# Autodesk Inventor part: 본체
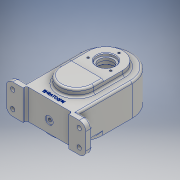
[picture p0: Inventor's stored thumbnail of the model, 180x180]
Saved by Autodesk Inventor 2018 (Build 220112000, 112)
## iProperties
Created: 2021-05
Part Number: 본체
Material: 알루미늄 6061
Document SubType Name: Modeling
Designer: Admin
Density: 2.7 g/cm^3
Appearance: 알루미늄 - 평지
Mass: 756.201 g
Surface Area: 581.914 cm^2
Volume: 280.074 cm^3
Author: Admin
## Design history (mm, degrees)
sketch "스케치1"
  geometry: L1 (0, 22.5)-(0, -22.5); L2 (-40, 22.5)-(-40, -22.5); L3 (40, -22.5)-(40, 22.5); L4 (-56, 0)-(56, 0) reference; L5 (0, -87.5)-(0, 87.5) reference; A1 r 40 centre (0, 22.5) between (40, 22.5) and (-40, 22.5); A2 r 40 centre (0, -22.5) between (-40, -22.5) and (40, -22.5); 2 further points
  constraints: 8 end point, 4 point on circle, 4 tangent, 2 centre point, 1 midpoint, 1 parallel, 1 vertical, 2 other
  dimensions: "d0" = 40 radius of A1; "d1" = 45 distance of L1.start L1.end
extrude "돌출1" new body sketch "스케치1" distance "d2" = 49; taper "d3" = 0 deg
sketch "스케치2"
  geometry: L1 (40, -22.5)-(40, -59.5); L2 (40, -59.5)-(61, -59.5); L3 (61, -59.5)-(61, -69.5); L4 (61, -69.5)-(35, -69.5); L5 (35, -69.5)-(35, -64.5); L6 (35, -64.5)-(-35, -64.5); L7 (-35, -64.5)-(-35, -69.5); L8 (-35, -69.5)-(-61, -69.5); L9 (-61, -69.5)-(-61, -59.5); L10 (-61, -59.5)-(-40, -59.5); L11 (-40, -22.5)-(-40, 22.5) reference; L12 (-40, -59.5)-(-40, -22.5); L13 (0, -96.5)-(0, 92.5) reference; A1 r 40 centre (0, -22.5) between (-40, -22.5) and (40, -22.5) reference; 1 further point
  constraints: 22 end point, 9 perpendicular, 1 collinear, 1 tangent, 1 vertical, 2 other
  dimensions: "d4" = 70 distance between parallel lines of L5 L7; "d5" = 10 distance of L8.end L9.end; "d6" = 10 distance of L2.end L3.end; "d7" = 47 distance from line of A1.centre L8; "d8" = 47 distance from line of A1.centre L4; "d9" = 5 distance between parallel lines of L6 L8; "d87" = 122 distance between parallel lines of L9 L3
extrude "돌출2" join sketch "스케치2" distance "d10" = 46; taper "d11" = 0 deg
node "작업 평면1"
sketch "스케치4"
  geometry: L1 (-40, -49)-(40, -49) reference; C1 r 6 at (0, -28); 1 further point
  constraints: 1 centre point
  dimensions: "d14" = 12 diameter of C1; "d15" = 21 distance from line of L1 C1.centre
extrude "돌출3" join sketch "스케치4" distance "d16" = 3; taper "d17" = 0 deg
sketch "스케치5"
  geometry: C1 r 6 at (0, -28); A1 r 6 centre (0, -28) between (0, -22) and (0, -34) reference; 1 further point
  constraints: 1 centre point, 1 coincident
  dimensions: "d18" = 12 diameter of C1
extrude "돌출4" join sketch "스케치5" distance "d19" = 3; taper "d20" = 0 deg
sketch "스케치6"
  geometry: L1 (0, 22.5)-(0, -22.5); L2 (-30, 22.5)-(-30, -22.5); L3 (30, -22.5)-(30, 22.5); A1 r 40 centre (0, 22.5) between (40, 22.5) and (-40, 22.5) reference; A2 r 40 centre (0, -22.5) between (-40, -22.5) and (40, -22.5) reference; A3 r 30 centre (0, 22.5) between (30, 22.5) and (-30, 22.5); A4 r 30 centre (0, -22.5) between (-30, -22.5) and (30, -22.5); 2 further points
  constraints: 8 end point, 4 point on circle, 4 tangent, 2 centre point, 1 midpoint, 1 parallel, 1 vertical
  dimensions: "d21" = 60 diameter of A4
extrude "돌출5" cut sketch "스케치6" distance "d22" = 41; taper "d23" = 0 deg
sketch "스케치7"
  geometry: L1 (0, 22.5)-(0, -22.5); L2 (-35, 22.5)-(-35, -22.5); L3 (35, -22.5)-(35, 22.5); A1 r 40 centre (0, 22.5) between (40, 22.5) and (-40, 22.5) reference; A2 r 40 centre (0, -22.5) between (-40, -22.5) and (40, -22.5) reference; A3 r 35 centre (0, 22.5) between (35, 22.5) and (-35, 22.5); A4 r 35 centre (0, -22.5) between (-35, -22.5) and (35, -22.5); 8 further points
  constraints: 8 end point, 6 point on circle, 4 coincident, 4 tangent, 2 centre point, 1 midpoint, 1 parallel, 1 vertical
  dimensions: "d24" = 70 diameter of A4
hole "구멍1" sketch "스케치7" at (0, 57.5), (35, 22.5), (-35, 22.5), (-35, -22.5), (0, -57.5), (35, -22.5) diameter "d25" = 3.242; stored, may be unused: countersink angle "d29" = 90 deg, drill point angle "d31" = 118 deg; dims "d26" = 8, "d27" = 4, "d28" = 2, "d30" = 10
sketch "스케치12"
  geometry: 1 further point
sketch "스케치13"
  geometry: L1 (0, 22.5)-(0, -22.5); L2 (-26, 22.5)-(-26, -22.5); L3 (26, -22.5)-(26, 22.5); A1 r 30 centre (0, 22.5) between (30, 22.5) and (-30, 22.5) reference; A2 r 30 centre (0, -22.5) between (-30, -22.5) and (30, -22.5) reference; A3 r 26 centre (0, 22.5) between (26, 22.5) and (-26, 22.5); A4 r 26 centre (0, -22.5) between (-26, -22.5) and (26, -22.5); 2 further points
  constraints: 8 end point, 4 point on circle, 4 tangent, 2 centre point, 1 midpoint, 1 parallel, 1 vertical
  dimensions: "d45" = 52 diameter of A4
extrude "돌출9" join sketch "스케치13" distance "d46" = 11; taper "d47" = 0 deg
sketch "스케치14"
  geometry: L1 (-26, 22.5)-(-26, -22.5) reference; L2 (26, 22.5)-(26, -22.5) reference; L3 (26, 22.5)-(26, -7.5); L4 (26, -7.5)-(-26, -7.5); L5 (-26, -7.5)-(-26, 22.5); A1 r 26 centre (0, 22.5) between (26, 22.5) and (-26, 22.5) reference; A2 r 26 centre (0, 22.5) between (26, 22.5) and (-26, 22.5); 1 further point
  constraints: 6 end point, 2 point on circle, 1 centre point, 1 coincident, 1 parallel, 1 point on line
  dimensions: "d48" = 30 distance from line of A2.centre L4
extrude "돌출10" cut sketch "스케치14" distance "d49" = 3; taper "d50" = 0 deg
sketch "스케치15"
  geometry: C1 r 14 at (0, 22.5); A1 r 26 centre (0, 22.5) between (26, 22.5) and (-26, 22.5) reference; 1 further point
  constraints: 1 centre point, 1 coincident
  dimensions: "d51" = 28 diameter of C1
extrude "돌출11" cut sketch "스케치15" distance "d52" = 4; taper "d53" = 0 deg
sketch "스케치16"
  geometry: C1 r 14 at (0, 0) reference; C2 r 11 at (0, 0); 1 further point
  constraints: 1 centre point, 1 coincident
  dimensions: "d54" = 22 diameter of C2
extrude "돌출12" cut sketch "스케치16" distance "d55" = 12; taper "d56" = 0 deg
sketch "스케치17"
  geometry: C1 r 11 at (0, 22.5) reference; C2 r 14 at (0, 22.5); 1 further point
  constraints: 1 centre point, 1 coincident
  dimensions: "d57" = 28 diameter of C2
extrude "돌출13" cut sketch "스케치17" distance "d58" = 8; taper "d59" = 0 deg
sketch "스케치18"
  geometry: C1 r 14 at (0, -22.5); A1 r 26 centre (0, -22.5) between (-26, -22.5) and (26, -22.5) reference; 1 further point
  constraints: 1 centre point, 1 coincident
  dimensions: "d60" = 28 diameter of C1
extrude "돌출14" cut sketch "스케치18" distance "d61" = 8; taper "d62" = 0 deg
sketch "스케치19"
  geometry: C1 r 14 at (0, 0) reference; C2 r 10 at (0, 0); 1 further point
  constraints: 1 centre point, 1 coincident
  dimensions: "d63" = 20 diameter of C2
extrude "돌출15" cut sketch "스케치19" distance "d64" = 4; taper "d65" = 0 deg
sketch "스케치20"
  geometry: C1 r 6 at (0, 0) reference; 2 further points
  constraints: 1 coincident
hole "구멍2" sketch "스케치20" at (0, 0) diameter "d66" = 4.917; stored, may be unused: countersink angle "d70" = 90 deg, drill point angle "d72" = 118 deg; dims "d67" = 300, "d68" = 4, "d69" = 2, "d71" = 17.1
sketch "스케치21"
  geometry: C1 r 2.458 at (35, -28) reference; C2 r 6 at (35, -28); 1 further point
  constraints: 1 centre point, 1 coincident
  dimensions: "d73" = 12 diameter of C2
extrude "돌출16" cut sketch "스케치21" distance "d74" = 1; taper "d75" = 0 deg
sketch "스케치22" dims "d76" = 40
  geometry: L1 (-85.4, 0)-(85.4, 0) reference; L2 (0, -96.5)-(0, 92.5) reference; C1 r 14 at (0, 22.5) reference; 3 further points
  constraints: 1 coincident, 1 point on line, 1 vertical alignment, 2 other
hole "구멍3" sketch "스케치22" at (0, 42.5) diameter "d77" = 3.242; stored, may be unused: countersink angle "d81" = 90 deg, drill point angle "d83" = 118 deg; dims "d78" = 8, "d79" = 4, "d80" = 2, "d82" = 10
fillet "모깎기1" dims "d88" = 10, "d89" = 0.3, "d93" = 3, "d94" = 5
chamfer "모따기1" distance "d90" = 1; stored, may be unused: second distance "d91" = 2, angle "d92" = 45 deg
sketch "스케치23"
  geometry: C1 r 5.5 at (0, 7); C2 r 5.5 at (0, 33); A1 r 7 centre (0, 7) between (-7, 7) and (0, 0) reference; A2 r 10 centre (0, 33) between (0, 43) and (-10, 33) reference; 1 further point
  constraints: 2 centre point, 2 coincident
  dimensions: "d95" = 11 diameter of C1; "d103" = 11 diameter of C2
hole "구멍4" sketch "스케치23" at (0, 7), (0, 33) diameter "d96" = 6.6; stored, may be unused: countersink angle "d100" = 90 deg, drill point angle "d102" = 118 deg; dims "d97" = 8, "d98" = 11, "d99" = 2, "d101" = 10
sketch "스케치24"
  geometry: L1 (-32, -64.5)-(32, -64.5) reference; L2 (0, -96.508)-(0, 92.549) reference; L3 (-51, -69.5)-(-35, -69.5) reference; 2 further points
  constraints: 1 point on line, 1 other
  dimensions: "d105" = 12 distance from line of point (0, -57.5) L3
feature "엠보싱1" sketch "스케치24" dims "d0" = 40, "d1" = 45, "d106" = 0.5, "d107" = 0
node "솔리드1"
pattern_circular "원형 패턴1" dims angle "d85" = 360 deg
mirror "미러1"
